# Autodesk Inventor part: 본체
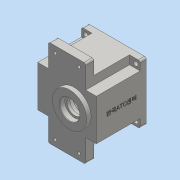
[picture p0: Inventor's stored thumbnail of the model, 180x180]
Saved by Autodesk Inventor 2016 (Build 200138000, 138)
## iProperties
Created: 2020-08
Part Number: 본체
Material: 일반
Document SubType Name: Modeling
Designer: User
Density: 1 g/cm^3
Appearance: 기본값
Author: User
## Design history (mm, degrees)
sketch "스케치1"
  geometry: L1 (47, -33)-(-47, -33); L2 (-47, -33)-(-47, 33); L3 (-47, 33)-(47, 33); L4 (47, 33)-(47, -33); L5 (47, -33)-(-47, 33); L6 (-47, -33)-(47, 33); L7 (-30, -70)-(30, -70); L8 (30, -70)-(30, 70); L9 (30, 70)-(-30, 70); L10 (-30, 70)-(-30, -70); L11 (-30, -70)-(30, 70); L12 (30, -70)-(-30, 70); 1 further point
  constraints: 24 end point, 4 midpoint, 4 parallel, 2 horizontal, 2 perpendicular
  dimensions: "d0" = 66 distance of L3.end L1.start; "d1" = 94 distance of L1.start L1.end; "d2" = 60 distance of L7.start L7.end; "d3" = 140 distance of L7.end L8.end
extrude "돌출1" new body sketch "스케치1" distance "d4" = 13; taper "d5" = 0 deg
sketch "스케치2"
  geometry: L1 (-47, 47)-(47, 47); L2 (47, 47)-(47, -47); L3 (47, -47)-(-47, -47); L4 (-47, -47)-(-47, 47); L5 (-47, 47)-(47, -47); L6 (47, 47)-(-47, -47); 1 further point
  constraints: 12 end point, 2 midpoint, 2 parallel, 1 horizontal, 1 perpendicular
  dimensions: "d6" = 94 distance of L2.end L3.end; "d7" = 94 distance of L1.end L2.end
extrude "돌출2" join sketch "스케치2" distance "d8" = 67; taper "d9" = 0 deg
sketch "스케치3"
  geometry: L1 (30, 47)-(30, 33) reference; L2 (30, 33)-(47, 33) reference; L3 (47, 33)-(47, 47) reference; L4 (47, 47)-(30, 47) reference; L5 (-30, 33)-(-30, 47) reference; L6 (-30, 47)-(-47, 47) reference; L7 (-47, 47)-(-47, 33) reference; L8 (-47, 33)-(-30, 33) reference; L9 (-30, -33)-(-47, -33) reference; L10 (-47, -33)-(-47, -47) reference; L11 (-47, -47)-(-30, -47) reference; L12 (-30, -47)-(-30, -33) reference; L13 (47, -33)-(30, -33) reference; L14 (30, -33)-(30, -47) reference; L15 (30, -47)-(47, -47) reference; L16 (47, -47)-(47, -33) reference; 1 further point
extrude "돌출3" cut sketch "스케치3" distance "d10" = 70; taper "d11" = 0 deg
sketch "스케치4"
  geometry: C1 r 27.5 at (11, 0); 1 further point
  constraints: 1 centre point, 1 horizontal alignment
  dimensions: "d12" = 55 diameter of C1; "d13" = 11 distance of point (0, 0) C1.centre
extrude "돌출4" join sketch "스케치4" distance "d14" = 7; taper "d15" = 0 deg
sketch "스케치5"
  geometry: C1 r 43 at (0, 0); 1 further point
  constraints: 1 centre point, 1 coincident
  dimensions: "d16" = 86 diameter of C1
extrude "돌출5" cut sketch "스케치5" distance "d17" = 9; taper "d18" = 0 deg
sketch "스케치6"
  geometry: C1 r 40 at (0, 0); 1 further point
  constraints: 1 centre point, 1 coincident
  dimensions: "d19" = 80 diameter of C1
extrude "돌출6" cut sketch "스케치6" distance "d20" = 62; taper "d21" = 0 deg
sketch "스케치7"
  geometry: C1 r 21 at (11, 0); C2 r 15 at (-20, 0); 1 further point
  constraints: 2 centre point, 2 horizontal alignment
  dimensions: "d22" = 30 diameter of C2; "d23" = 42 diameter of C1; "d24" = 11 distance of point (0, 0) C1.centre; "d25" = 20 distance of point (0, 0) C2.centre
extrude "돌출7" join sketch "스케치7" distance "d26" = 7; taper "d27" = 0 deg
sketch "스케치8"
  geometry: C1 r 16 at (0, 0); A1 r 21 centre (0, 0) between (-18.984, -8.978) and (-18.984, 8.978) reference; 1 further point
  constraints: 1 centre point, 1 coincident
  dimensions: "d28" = 32 diameter of C1
extrude "돌출8" cut sketch "스케치8" distance "d29" = 8.3; taper "d30" = 0 deg
sketch "스케치9"
  geometry: C1 r 16 at (0, 0) reference; C2 r 12.5 at (0, 0); 1 further point
  constraints: 1 centre point, 1 coincident
  dimensions: "d31" = 25 diameter of C2
extrude "돌출9" cut sketch "스케치9" distance "d32" = 4.7; taper "d33" = 0 deg
sketch "스케치10"
  geometry: C1 r 12.5 at (0, 0) reference; C2 r 17.5 at (0, 0); 1 further point
  constraints: 1 centre point, 1 coincident
  dimensions: "d34" = 35 diameter of C2
extrude "돌출10" cut sketch "스케치10" distance "d35" = 10; taper "d36" = 0 deg
sketch "스케치11"
  geometry: C1 r 17.5 at (11, 0) reference; C2 r 11 at (-20, 0); A1 r 21 centre (11, 0) between (-7.984, -8.978) and (-7.984, 8.978) reference; A2 r 15 centre (-20, 0) between (-7.984, 8.978) and (-7.984, -8.978) reference; 1 further point
  constraints: 1 centre point, 1 coincident
  dimensions: "d37" = 22 diameter of C2
extrude "돌출11" cut sketch "스케치11" distance "d38" = 7; taper "d39" = 0 deg
sketch "스케치12"
  geometry: C1 r 11 at (0, 0) reference; C2 r 9.5 at (0, 0); 1 further point
  constraints: 1 centre point, 1 coincident
  dimensions: "d40" = 19 diameter of C2
extrude "돌출12" cut sketch "스케치12" distance "d41" = 3; taper "d42" = 0 deg
sketch "스케치13"
  geometry: A1 r 36 centre (0, 0) between (-3.994, 35.778) and (3.994, 35.778); A2 r 4 centre (0, 36) between (-3.995, 36.19) and (3.995, 36.19); A3 r 3 centre (-6.992, 36.333) between (-4.045, 35.772) and (-7.559, 39.279); A4 r 3 centre (6.992, 36.333) between (7.559, 39.279) and (4.045, 35.772); A5 r 40 centre (0, 0) between (7.559, 39.279) and (-7.559, 39.279) reference; 1 further point
  constraints: 17 point on circle, 4 centre point, 4 tangent, 1 coincident, 1 vertical alignment
  dimensions: "d43" = 72 diameter of A1; "d44" = 8 diameter of A2; "d45" = 6 diameter of A3; "d46" = 6 diameter of A4
extrude "돌출13" join sketch "스케치13" distance "d47" = 62; taper "d48" = 0 deg
sketch "스케치14"
  geometry: C1 r 43 at (0, 0) reference; A1 r 40 centre (0, 0) between (-7.559, 39.279) and (7.559, 39.279) reference; A2 r 3 centre (-6.992, 36.333) between (-3.995, 36.19) and (-7.559, 39.279) reference; A3 r 4 centre (0, 36) between (-3.995, 36.19) and (3.995, 36.19) reference; A4 r 3 centre (6.992, 36.333) between (7.559, 39.279) and (3.995, 36.19) reference; 2 further points
  constraints: 1 coincident
hole "구멍1" sketch "스케치14" at (0, 36) diameter "d49" = 3.242; stored, may be unused: countersink angle "d53" = 90 deg, drill point angle "d55" = 118 deg; dims "d50" = 7, "d51" = 4, "d52" = 2, "d54" = 9
sketch "스케치15"
  geometry: L1 (47, 47)-(-47, 47) reference; L2 (47, -47)-(47, 47) reference; 2 further points
  dimensions: "d56" = 7 distance from line of L1 point (40, 40); "d57" = 7 distance from line of L2 point (40, 40)
hole "구멍2" sketch "스케치15" at (40, 40) diameter "d58" = 7; stored, may be unused: countersink angle "d62" = 90 deg, drill point angle "d64" = 0 deg; dims "d59" = 7, "d60" = 4, "d61" = 2, "d63" = 10
sketch "스케치16"
  geometry: L1 (30, 33)-(30, 70) reference; L2 (30, 70)-(-30, 70) reference; 5 further points
  constraints: 2 horizontal alignment, 2 vertical alignment
  dimensions: "d71" = 11 distance from line of L1 point (19, 60); "d72" = 38 distance of point (-19, 60) point (19, 60); "d73" = 120 distance of point (19, -60) point (19, 60); "d74" = 10 distance from line of L2 point (19, 60)
hole "구멍3" sketch "스케치16" at (19, 60), (-19, 60), (-19, -60), (19, -60) diameter "d75" = 4.5; stored, may be unused: countersink angle "d79" = 90 deg, drill point angle "d81" = 0 deg; dims "d76" = 7, "d77" = 10, "d78" = 5, "d80" = 13
chamfer "모따기1" distance "d82" = 0.8; stored, may be unused: second distance "d83" = 2, angle "d84" = 30 deg
chamfer "모따기2" distance "d85" = 1; stored, may be unused: second distance "d86" = 2, angle "d87" = 30 deg
fillet "모깎기1" dims "d88" = 3
fillet "모깎기3" dims "d90" = 3
fillet "모깎기4" dims "d91" = 3
sketch "스케치17"
  geometry: L1 (-11, 80)-(77, 80) reference; L2 (66, 0)-(0, 0) reference; 3 further points
  constraints: 1 midpoint, 1 vertical alignment, 1 other
  dimensions: "d92" = 40 distance from line of point (33, 40) L1
feature "엠보싱1" sketch "스케치17" dims "d0" = 66, "d1" = 94, "d93" = 0.5, "d94" = 0
fillet "모깎기5" dims "d95" = 3
node "솔리드1"
mirror "대칭1"
pattern_linear "직사각형 패턴1" dims "d67" = 80
node "투영된 루프1"
node "투영된 루프2"
node "투영된 루프3"
node "투영된 루프4"
node "투영된 루프5"
node "투영된 루프6"
node "투영된 루프7"
node "투영된 루프8"
node "투영된 루프9"
